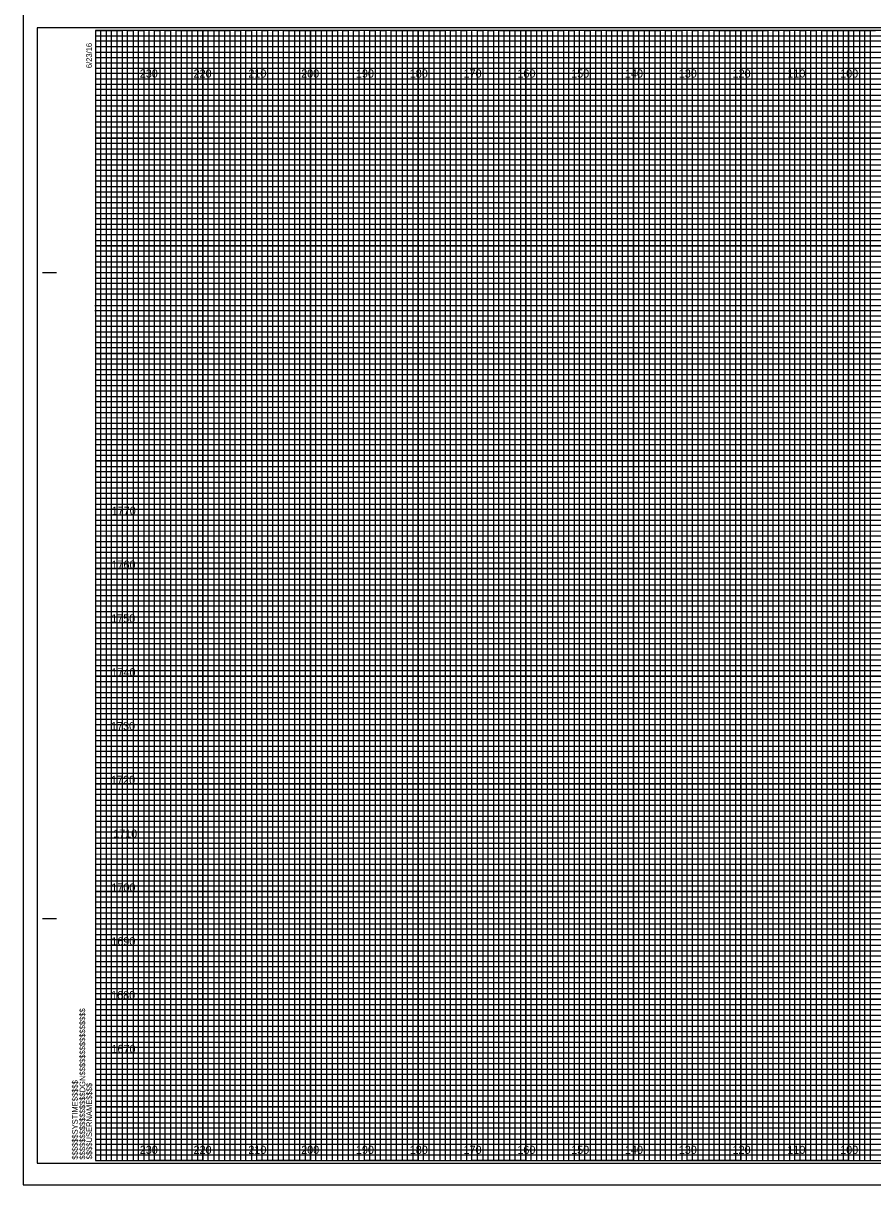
# Model space of a CAD drawing. Extents: x -13 to 1780, y -15 to 3284.
# Drawn here: x 726.7 to 884.6, y 431.6 to 647.5 of the extents above; entities that cross this region are included whole.
import ezdxf

# ---------------------------------------------------------------- set-up
doc = ezdxf.new("R2010")
doc.units = 0
for name, color, linetype in [('Prop Retaining Wall', 7, 'Continuous'), ('Prop SS Cut Line', 7, 'Continuous'), ('Prop SS Fill Line', 7, 'Continuous'), ('Prop SS Transition Line', 7, 'Continuous'), ('Prop XS Earthwork Shape', 7, 'Continuous'), ('Prop XS Noise Wall', 7, 'Continuous'), ('Prop XS Station Labels', 7, 'Continuous'), ('Raster_Level_0', 7, 'Continuous'), ('Scratch_Level_3', 7, 'Continuous'), ('Scratch_Level_7', 7, 'Continuous'), ('Typical Bridge Rail CELL', 7, 'Continuous')]:
    doc.layers.add(name, color=color, linetype=linetype)

msp = doc.modelspace()

# ---------------------------------------------------------------- linework, layer by layer
at = {"layer": 'Prop Retaining Wall'}
for p, q in [((730.26, 601.12), (732.76, 601.12)), ((730.36, 601.12), (732.86, 601.12)), ((730.26, 481.12), (732.76, 481.12)), ((730.36, 481.12), (732.86, 481.12)), ((740.06, 436.12), (740.06, 436.12)), ((740.06, 436.12), (740.06, 436.12)), ((740.06, 436.12), (740.06, 436.12)), ((740.06, 436.12), (740.06, 436.12)), ((740.06, 436.12), (740.06, 436.12)), ((740.06, 436.12), (740.06, 436.12)), ((740.06, 436.12), (740.06, 436.12))]:
    msp.add_line(p, q, dxfattribs=at)
msp.add_lwpolyline([(1060.06, 646.12), (740.06, 646.12), (740.06, 436.12), (1060.06, 436.12)], close=True, dxfattribs=at)
at = {"layer": 'Prop SS Cut Line'}
for points in [[(740.06, 646.12), (745.06, 646.12), (745.06, 436.12), (755.06, 436.12), (755.06, 646.12), (765.06, 646.12), (765.06, 436.12), (775.06, 436.12), (775.06, 646.12), (785.06, 646.12), (785.06, 436.12), (795.06, 436.12), (795.06, 646.12), (805.06, 646.12), (805.06, 436.12), (815.06, 436.12), (815.06, 646.12), (825.06, 646.12), (825.06, 436.12), (835.06, 436.12), (835.06, 646.12), (845.06, 646.12), (845.06, 436.12), (855.06, 436.12), (855.06, 646.12), (865.06, 646.12), (865.06, 436.12), (875.06, 436.12), (875.06, 646.12), (885.06, 646.12)], [(740.06, 641.12), (1015.06, 641.12)], [(740.06, 621.12), (1060.06, 621.12), (1060.06, 631.12), (740.06, 631.12)], [(740.06, 601.12), (1060.06, 601.12), (1060.06, 611.12), (740.06, 611.12)], [(740.06, 581.12), (1060.06, 581.12), (1060.06, 591.12), (740.06, 591.12)], [(740.06, 561.12), (1060.06, 561.12), (1060.06, 571.12), (740.06, 571.12)], [(740.06, 541.12), (1060.06, 541.12), (1060.06, 551.12), (740.06, 551.12)], [(740.06, 521.12), (1060.06, 521.12), (1060.06, 531.12), (740.06, 531.12)], [(740.06, 501.12), (1060.06, 501.12), (1060.06, 511.12), (740.06, 511.12)], [(740.06, 481.12), (1060.06, 481.12), (1060.06, 491.12), (740.06, 491.12)], [(740.06, 461.12), (1060.06, 461.12), (1060.06, 471.12), (740.06, 471.12)], [(740.06, 441.12), (1060.06, 441.12), (1060.06, 451.12), (740.06, 451.12)]]:
    msp.add_lwpolyline(points, dxfattribs=at)
at = {"layer": 'Prop SS Fill Line'}
for p, q in [((750.06, 646.12), (740.06, 646.12)), ((750.06, 436.12), (750.06, 646.12)), ((770.06, 646.12), (760.06, 646.12)), ((760.06, 646.12), (760.06, 436.12)), ((770.06, 436.12), (770.06, 646.12)), ((790.06, 646.12), (780.06, 646.12)), ((780.06, 646.12), (780.06, 436.12)), ((790.06, 436.12), (790.06, 646.12)), ((810.06, 646.12), (800.06, 646.12)), ((800.06, 646.12), (800.06, 436.12)), ((810.06, 436.12), (810.06, 646.12)), ((830.06, 646.12), (820.06, 646.12)), ((820.06, 646.12), (820.06, 436.12)), ((830.06, 436.12), (830.06, 646.12)), ((850.06, 646.12), (840.06, 646.12)), ((840.06, 646.12), (840.06, 436.12)), ((850.06, 436.12), (850.06, 646.12)), ((870.06, 646.12), (860.06, 646.12)), ((860.06, 646.12), (860.06, 436.12)), ((870.06, 436.12), (870.06, 646.12)), ((890.06, 646.12), (880.06, 646.12)), ((880.06, 646.12), (880.06, 436.12)), ((760.06, 436.12), (750.06, 436.12)), ((780.06, 436.12), (770.06, 436.12)), ((800.06, 436.12), (790.06, 436.12)), ((820.06, 436.12), (810.06, 436.12)), ((840.06, 436.12), (830.06, 436.12)), ((860.06, 436.12), (850.06, 436.12)), ((880.06, 436.12), (870.06, 436.12))]:
    msp.add_line(p, q, dxfattribs=at)
for points in [[(740.06, 636.12), (1060.06, 636.12), (1060.06, 626.12), (740.06, 626.12)], [(740.06, 616.12), (1060.06, 616.12), (1060.06, 606.12), (740.06, 606.12)], [(740.06, 596.12), (1060.06, 596.12), (1060.06, 586.12), (740.06, 586.12)], [(740.06, 576.12), (1060.06, 576.12), (1060.06, 566.12), (740.06, 566.12)], [(740.06, 556.12), (1060.06, 556.12), (1060.06, 546.12), (740.06, 546.12)], [(740.06, 536.12), (1060.06, 536.12), (1060.06, 526.12), (740.06, 526.12)], [(740.06, 516.12), (1060.06, 516.12), (1060.06, 506.12), (740.06, 506.12)], [(740.06, 496.12), (1060.06, 496.12), (1060.06, 486.12), (740.06, 486.12)], [(740.06, 476.12), (1060.06, 476.12), (1060.06, 466.12), (740.06, 466.12)], [(740.06, 456.12), (1060.06, 456.12), (1060.06, 446.12), (740.06, 446.12)]]:
    msp.add_lwpolyline(points, dxfattribs=at)
at = {"layer": 'Prop SS Transition Line'}
for p, q in [((740.06, 645.12), (1000.06, 645.12)), ((1000.06, 644.1), (740.06, 644.1)), ((740.06, 644.1), (740.06, 643.12)), ((740.06, 643.12), (1000.06, 643.12)), ((1000.06, 642.01), (740.06, 642.01)), ((740.06, 642.01), (740.06, 640.12)), ((740.06, 640.12), (1060.06, 640.12))]:
    msp.add_line(p, q, dxfattribs=at)
for points in [[(740.06, 639.12), (1010.06, 639.12), (1060.06, 639.12), (1060.06, 638.12), (740.06, 638.12)], [(740.06, 637.12), (1060.06, 637.12), (1060.06, 635.12), (740.06, 635.12)], [(740.06, 634.12), (1060.06, 634.12), (1060.06, 633.12), (740.06, 633.1)], [(740.06, 632.12), (1060.06, 632.12), (1060.06, 630.12), (740.06, 630.12)], [(740.06, 629.12), (1060.06, 629.12), (1060.06, 628.12), (740.06, 628.12)], [(740.06, 627.12), (1060.06, 627.12), (1060.06, 625.12), (740.06, 625.12)], [(740.06, 624.12), (1060.06, 624.12), (1060.06, 623.12), (740.06, 623.12)], [(740.06, 622.12), (1060.06, 622.12), (1060.06, 620.12), (740.06, 620.12)], [(740.06, 619.12), (1060.06, 619.12), (1060.06, 618.12), (740.06, 618.12)], [(740.06, 617.12), (1060.06, 617.12), (1060.06, 615.12), (740.06, 615.12)], [(740.06, 614.12), (1060.06, 614.12), (1060.06, 613.12), (740.06, 613.12)], [(740.06, 612.12), (1060.06, 612.12), (1060.06, 610.07), (1060.06, 609.12), (1060.06, 608.12), (740.06, 608.12)], [(740.06, 610.12), (1060.06, 610.12), (1060.06, 609.12), (740.06, 609.12)], [(740.06, 607.12), (1060.06, 607.12), (1060.06, 605.12), (740.06, 605.15)], [(740.06, 605.15), (1060.06, 605.12), (1060.06, 604.12), (740.06, 604.12)], [(740.06, 603.12), (1060.06, 603.12), (1060.06, 602.12), (740.06, 602.12)], [(740.06, 600.12), (1060.06, 600.12), (1060.06, 599.12), (740.06, 599.12)], [(740.06, 598.12), (1060.06, 598.12), (1060.06, 597.12), (740.06, 597.12)], [(739.99, 595.01), (1060.06, 595.01), (1060.06, 594), (739.99, 594)], [(740.06, 593.12), (1060.06, 593.12), (1060.06, 592.12), (740.06, 592.12)], [(740.06, 590.12), (1060.06, 590.12), (1060.06, 589.12), (740.06, 589.12)], [(740.06, 588.12), (1060.06, 588.12), (1060.06, 587.12), (740.06, 587.12)], [(740.06, 585.12), (1060.06, 585.12), (1060.06, 584.12), (740.06, 584.12)], [(740.06, 583.12), (1060.06, 583.12), (1060.06, 582.12), (740.06, 582.12)], [(740.06, 580.12), (1060.06, 580.12), (1060.06, 579.12), (740.06, 579.12)], [(740.06, 578.12), (1060.06, 578.12), (1060.06, 577.12), (740.06, 577.12)], [(740.06, 575.12), (1060.06, 575.12), (1060.05, 574.1), (740.06, 574.12)], [(740.06, 573.12), (1060.06, 573.12), (1060.06, 572.12), (740.06, 572.12)], [(740.06, 570.12), (1060.06, 570.12), (1060.06, 569.12), (740.06, 569.12)], [(740.06, 568.12), (1060.06, 568.12), (1060.06, 567.12), (740.06, 567.12)], [(740.06, 565.12), (1060.06, 565.12), (1060.06, 564.12), (740.06, 564.12)], [(740.06, 563.12), (1060.06, 563.12), (1060.06, 562.12), (740.06, 562.12)], [(740.06, 560.12), (1060.06, 560.12), (1060.06, 559.12), (740.06, 559.12)], [(740.06, 558.12), (1060.06, 558.12), (1060.06, 557.12), (740.06, 557.12)], [(740.06, 555.12), (1060.06, 555.12), (1060.06, 554.12), (740.06, 554.12)], [(740.06, 553.11), (1060.13, 553.03), (1060.06, 552.12), (740.06, 552.12)], [(740.06, 550.12), (1060.06, 550.12), (1060.06, 549.12), (740.06, 549.12)], [(740.06, 548.12), (1060.06, 548.12), (1060.06, 547.12), (740.06, 547.12)], [(740.06, 545.12), (1060.06, 545.12), (1060.06, 544.12), (740.06, 544.12)], [(740.06, 543.12), (1060.06, 543.12), (1060.06, 542.12), (740.06, 542.12)], [(740.06, 540.12), (1060.06, 540.12), (1060.06, 539.12), (740.06, 539.12)], [(740.06, 538.12), (1060.06, 538.12), (1060.06, 537.12), (740.06, 537.12)], [(740.06, 535.12), (1060.06, 535.12), (1060.06, 534.12), (740.06, 534.12)], [(740.06, 533.12), (1060.06, 533.12), (1060.06, 532.12), (740.06, 532.12)], [(740.06, 530.12), (1060.06, 530.12), (1060.06, 529.12), (740.06, 529.12)], [(740.06, 528.12), (1060.06, 528.12), (1060.06, 527.12), (740.06, 527.12)], [(740.06, 525.12), (1060.06, 525.12), (1060.06, 524.12), (740.06, 524.12)], [(740.06, 523.12), (1060.06, 523.12), (1060.06, 522.12), (740.06, 522.12)], [(740.06, 520.12), (1060.06, 520.12), (1060.06, 519.12), (740.06, 519.12)], [(740.06, 518.12), (1060.06, 518.12), (1060.06, 517.12), (740.06, 517.12)], [(740.06, 515.12), (1060.06, 515.12), (1060.05, 514.1), (740.06, 514.12)], [(740.06, 513.12), (1060.06, 513.12), (1060.06, 512.12), (740.06, 512.12)], [(740.06, 510.12), (1060.06, 510.12), (1060.06, 509.12), (740.06, 509.12)], [(740.06, 508.12), (1060.06, 508.12), (1060.06, 507.12), (740.06, 507.12)], [(740.06, 505.12), (1060.06, 505.12), (1060.06, 504.12), (740.06, 504.12)], [(740.06, 503.12), (1060.06, 503.12), (1060.06, 502.12), (740.06, 502.12)], [(740.06, 500.12), (1060.06, 500.12), (1060.06, 499.12), (740.06, 499.12)], [(740.06, 498.12), (1060.06, 498.12), (1060.06, 497.12), (740.06, 497.12)], [(740.06, 495.12), (1060.06, 495.12), (1060.06, 494.12), (740.06, 494.12)], [(740.06, 493.11), (1060.13, 493.03), (1060.06, 492.12), (740.06, 492.12)], [(740.06, 490.12), (1060.06, 490.12), (1060.06, 489.12), (740.06, 489.12)], [(740.06, 488.12), (1060.06, 488.12), (1060.06, 487.12), (740.06, 487.12)], [(740.06, 485.12), (1060.06, 485.12), (1060.06, 484.12), (740.06, 484.12)], [(740.06, 483.12), (1060.06, 483.12), (1060.06, 482.12), (740.06, 482.12)], [(740.06, 480.12), (1060.06, 480.12), (1060.06, 479.12), (740.06, 479.12)], [(740.06, 478.12), (1060.06, 478.12), (1060.06, 477.12), (740.06, 477.12)], [(740.06, 475.12), (1060.06, 475.12), (1060.06, 474.12), (740.06, 474.12)], [(740.06, 473.12), (1060.06, 473.12), (1060.06, 472.12), (740.06, 472.12)], [(740.06, 470.12), (1060.06, 470.12), (1060.06, 469.12), (740.06, 469.12)], [(740.06, 468.12), (1060.06, 468.12), (1060.06, 467.12), (740.06, 467.12)], [(740.06, 465.12), (1060.06, 465.12), (1060.06, 464.12), (740.06, 464.12)], [(740.06, 463.12), (1060.06, 463.12), (1060.06, 462.12), (740.06, 462.12)], [(740.06, 460.12), (1060.06, 460.12), (1060.06, 459.12), (740.06, 459.12)], [(740.06, 458.12), (1060.06, 458.12), (1060.06, 457.12), (740.06, 457.12)], [(740.06, 455.12), (1060.06, 455.12), (1060.06, 454.12), (740.06, 454.12)], [(740.06, 453.12), (1060.06, 453.12), (1060.06, 452.12), (740.06, 452.12)], [(740.06, 450.12), (1060.06, 450.12), (1060.06, 449.12), (740.06, 449.12)], [(740.06, 448.12), (1060.06, 448.12), (1060.06, 447.12), (740.06, 447.12)], [(740.06, 445.12), (1060.06, 445.12), (1060.06, 444.12), (740.06, 444.12)], [(740.06, 443.12), (1060.06, 443.12), (1060.06, 442.12), (740.06, 442.12)], [(740.06, 440.12), (1060.06, 440.12), (1060.06, 439.12), (740.06, 439.12)], [(740.06, 438.12), (1060.06, 438.12), (1060.06, 437.12), (740.06, 437.12)]]:
    msp.add_lwpolyline(points, dxfattribs=at)
at = {"layer": 'Prop XS Earthwork Shape'}
msp.add_lwpolyline([(726.66, 431.62), (1063.36, 431.62), (1063.36, 650.62), (726.66, 650.62)], close=True, dxfattribs=at)
at = {"layer": 'Prop XS Noise Wall'}
for p, q in [((750.06, 436.12), (750.06, 646.12)), ((760.06, 436.12), (760.06, 646.12)), ((770.06, 436.12), (770.06, 646.12)), ((780.06, 436.12), (780.06, 646.12)), ((790.06, 436.12), (790.06, 646.12)), ((800.06, 436.12), (800.06, 646.12)), ((810.06, 436.12), (810.06, 646.12)), ((820.06, 436.12), (820.06, 646.12)), ((830.06, 436.12), (830.06, 646.12)), ((840.06, 436.12), (840.06, 646.12)), ((850.06, 436.12), (850.06, 646.12)), ((860.06, 436.12), (860.06, 646.12)), ((870.06, 436.12), (870.06, 646.12)), ((880.06, 436.12), (880.06, 646.12)), ((740.06, 636.12), (1060.06, 636.12)), ((740.06, 626.12), (1060.06, 626.12)), ((740.06, 616.12), (1060.06, 616.12)), ((740.06, 606.12), (1060.06, 606.12)), ((740.06, 596.12), (1060.06, 596.12)), ((740.06, 586.12), (1060.06, 586.12)), ((740.06, 576.12), (1060.06, 576.12)), ((740.06, 566.12), (1060.06, 566.12)), ((740.06, 556.12), (1060.06, 556.12)), ((740.06, 546.12), (1060.06, 546.12)), ((740.06, 536.12), (1060.06, 536.12)), ((740.06, 526.12), (1060.06, 526.12)), ((740.06, 516.12), (1060.06, 516.12)), ((740.06, 506.12), (1060.06, 506.12)), ((740.06, 496.12), (1060.06, 496.12)), ((740.06, 486.12), (1060.06, 486.12)), ((740.06, 476.12), (1060.06, 476.12)), ((740.06, 466.12), (1060.06, 466.12)), ((740.06, 456.12), (1060.06, 456.12)), ((740.06, 446.12), (1060.06, 446.12))]:
    msp.add_line(p, q, dxfattribs=at)
at = {"layer": 'Prop XS Station Labels'}
for p, q in [((726.66, 650.62), (726.66, 431.62)), ((726.66, 431.62), (1063.36, 431.62))]:
    msp.add_line(p, q, dxfattribs=at)
at = {"layer": 'Scratch_Level_7'}
msp.add_lwpolyline([(729.26, 435.62), (1062.46, 435.62), (1062.46, 646.62), (729.26, 646.62)], close=True, dxfattribs=at)
at = {"layer": 'Typical Bridge Rail CELL'}
for points in [[(740.06, 436.12), (741.06, 436.12), (741.06, 646.12), (742.06, 646.12), (742.06, 436.12)], [(742.06, 436.12), (743.06, 436.12), (743.06, 646.12), (744.06, 646.12), (744.06, 436.12)], [(745.06, 436.12), (746.06, 436.12), (746.06, 646.12), (747.06, 646.12), (747.06, 436.12)], [(747.06, 436.12), (748.06, 436.12), (748.06, 646.12), (749.06, 646.12), (749.06, 436.12)], [(750.06, 436.12), (751.06, 436.12), (751.06, 646.12), (752.06, 646.12), (752.06, 436.12)], [(752.06, 436.12), (753.06, 436.12), (753.06, 646.12), (754.06, 646.12), (754.06, 436.12)], [(755.06, 436.12), (756.06, 436.12), (756.06, 646.12), (757.06, 646.12), (757.06, 436.12)], [(757.06, 436.12), (758.06, 436.12), (758.06, 646.12), (759.06, 646.12), (759.06, 436.12)], [(760.06, 436.12), (761.06, 436.12), (761.06, 646.12), (762.06, 646.12), (762.06, 436.12)], [(762.06, 436.12), (763.06, 436.12), (763.06, 646.12), (764.06, 646.12), (764.06, 436.12)], [(765.06, 436.12), (766.06, 436.12), (766.06, 646.12), (767.06, 646.12), (767.06, 436.12)], [(767.06, 436.12), (768.06, 436.12), (768.06, 646.12), (769.06, 646.12), (769.06, 436.12)], [(770.06, 436.12), (771.06, 436.12), (771.06, 646.12), (772.06, 646.12), (772.06, 436.12)], [(772.06, 436.12), (773.06, 436.12), (773.06, 646.12), (774.06, 646.12), (774.06, 436.12)], [(775.06, 436.12), (776.06, 436.12), (776.06, 646.12), (777.06, 646.12), (777.06, 436.12)], [(777.06, 436.12), (778.06, 436.12), (778.06, 646.12), (779.06, 646.12), (779.06, 436.12)], [(780.06, 436.12), (781.06, 436.12), (781.06, 646.12), (782.06, 646.12), (782.06, 436.12)], [(782.06, 436.12), (783.06, 436.12), (783.06, 646.12), (784.06, 646.12), (784.06, 436.12)], [(785.06, 436.12), (786.06, 436.12), (786.06, 646.12), (787.06, 646.12), (787.06, 436.12)], [(787.06, 436.12), (788.06, 436.12), (788.06, 646.12), (789.06, 646.12), (789.06, 436.12)], [(790.06, 436.12), (791.06, 436.12), (791.06, 646.12), (792.06, 646.12), (792.06, 436.12)], [(792.06, 436.12), (793.06, 436.12), (793.06, 646.12), (794.06, 646.12), (794.06, 436.12)], [(795.06, 436.12), (796.06, 436.12), (796.06, 646.12), (797.06, 646.12), (797.06, 436.12)], [(797.06, 436.12), (798.06, 436.12), (798.06, 646.12), (799.06, 646.12), (799.06, 436.12)], [(800.06, 436.12), (801.06, 436.12), (801.06, 646.12), (802.06, 646.12), (802.06, 436.12)], [(802.06, 436.12), (803.06, 436.12), (803.06, 646.12), (804.06, 646.12), (804.06, 436.12)], [(805.06, 436.12), (806.06, 436.12), (806.06, 646.12), (807.06, 646.12), (807.06, 436.12)], [(807.06, 436.12), (808.06, 436.12), (808.06, 646.12), (809.06, 646.12), (809.06, 436.12)], [(810.06, 436.12), (811.06, 436.12), (811.06, 646.12), (812.06, 646.12), (812.06, 436.12)], [(812.06, 436.12), (813.06, 436.12), (813.06, 646.12), (814.06, 646.12), (814.06, 436.12)], [(815.06, 436.12), (816.06, 436.12), (816.06, 646.12), (817.06, 646.12), (817.06, 436.12)], [(817.06, 436.12), (818.06, 436.12), (818.06, 646.12), (819.06, 646.12), (819.06, 436.12)], [(820.06, 436.12), (821.06, 436.12), (821.06, 646.12), (822.06, 646.12), (822.06, 436.12)], [(822.06, 436.12), (823.06, 436.12), (823.06, 646.12), (824.06, 646.12), (824.06, 436.12)], [(825.06, 436.12), (826.06, 436.12), (826.06, 646.12), (827.06, 646.12), (827.06, 436.12)], [(827.06, 436.12), (828.06, 436.12), (828.06, 646.12), (829.06, 646.12), (829.06, 436.12)], [(830.06, 436.12), (831.06, 436.12), (831.06, 646.12), (832.06, 646.12), (832.06, 436.12)], [(832.06, 436.12), (833.06, 436.12), (833.06, 646.12), (834.06, 646.12), (834.06, 436.12)], [(835.06, 436.12), (836.06, 436.12), (836.06, 646.12), (837.06, 646.12), (837.06, 436.12)], [(837.06, 436.12), (838.06, 436.12), (838.06, 646.12), (839.06, 646.12), (839.06, 436.12)], [(840.06, 436.12), (841.06, 436.12), (841.06, 646.12), (842.06, 646.12), (842.06, 436.12)], [(842.06, 436.12), (843.06, 436.12), (843.06, 646.12), (844.06, 646.12), (844.06, 436.12)], [(845.06, 436.12), (846.06, 436.12), (846.06, 646.12), (847.06, 646.12), (847.06, 436.12)], [(847.06, 436.12), (848.06, 436.12), (848.06, 646.12), (849.06, 646.12), (849.06, 436.12)], [(850.06, 436.12), (851.06, 436.12), (851.06, 646.12), (852.06, 646.12), (852.06, 436.12)], [(852.06, 436.12), (853.06, 436.12), (853.06, 646.12), (854.06, 646.12), (854.06, 436.12)], [(855.06, 436.12), (856.06, 436.12), (856.06, 646.12), (857.06, 646.12), (857.06, 436.12)], [(857.06, 436.12), (858.06, 436.12), (858.06, 646.12), (859.06, 646.12), (859.06, 436.12)], [(860.06, 436.12), (861.06, 436.12), (861.06, 646.12), (862.06, 646.12), (862.06, 436.12)], [(862.06, 436.12), (863.06, 436.12), (863.06, 646.12), (864.06, 646.12), (864.06, 436.12)], [(865.06, 436.12), (866.06, 436.12), (866.06, 646.12), (867.06, 646.12), (867.06, 436.12)], [(867.06, 436.12), (868.06, 436.12), (868.06, 646.12), (869.06, 646.12), (869.06, 436.12)], [(870.06, 436.12), (871.06, 436.12), (871.06, 646.12), (872.06, 646.12), (872.06, 436.12)], [(872.06, 436.12), (873.06, 436.12), (873.06, 646.12), (874.06, 646.12), (874.06, 436.12)], [(875.06, 436.12), (876.06, 436.12), (876.06, 646.12), (877.06, 646.12), (877.06, 436.12)], [(877.06, 436.12), (878.06, 436.12), (878.06, 646.12), (879.06, 646.12), (879.06, 436.12)], [(880.06, 436.12), (881.06, 436.12), (881.06, 646.12), (882.06, 646.12), (882.06, 436.12)], [(882.06, 436.12), (883.06, 436.12), (883.06, 646.12), (884.06, 646.12), (884.06, 436.12)]]:
    msp.add_lwpolyline(points, dxfattribs=at)

# ---------------------------------------------------------------- texts
at = {"layer": 'Prop Retaining Wall'}
for s, p in [('6/23/16', (739.41, 639.12)), ('$$$$$$$$$$$$$$$$DGN$$$$$$$$$$$$$$$$', (738.18, 436.3)), ('$$$$$$SYSTIME$$$$$', (736.8, 436.3)), ('$$$$USERNAME$$$$', (739.44, 436.35))]:
    msp.add_text(s, height=1.05, rotation=90, dxfattribs=at).set_placement(p)
at = {"layer": 'Raster_Level_0'}
for s, p in [('230', (748.32, 637.37)), ('220', (758.32, 637.37)), ('210', (768.5, 637.37)), ('200', (778.32, 637.37)), ('190', (788.5, 637.37)), ('180', (798.5, 637.37)), ('170', (808.5, 637.37)), ('160', (818.5, 637.37)), ('150', (828.5, 637.37)), ('140', (838.5, 637.37)), ('130', (848.5, 637.37)), ('120', (858.5, 637.37)), ('110', (868.68, 637.37)), ('100', (878.5, 637.37)), ('230', (748.32, 437.37)), ('220', (758.32, 437.37)), ('210', (768.5, 437.37)), ('200', (778.32, 437.37)), ('190', (788.5, 437.37)), ('180', (798.5, 437.37)), ('170', (808.5, 437.37)), ('160', (818.5, 437.37)), ('150', (828.5, 437.37)), ('140', (838.5, 437.37)), ('130', (848.5, 437.37)), ('120', (858.5, 437.37)), ('110', (868.68, 437.37)), ('100', (878.5, 437.37))]:
    msp.add_text(s, height=1.5, dxfattribs=at).set_placement(p)
at = {"layer": 'Scratch_Level_3'}
for s, p in [('1770', (743.1, 556.12)), ('1760', (743.06, 546.12)), ('1750', (743.01, 536.12)), ('1740', (743.06, 526.12)), ('1730', (742.98, 516.12)), ('1720', (742.99, 506.12)), ('1710', (743.37, 496.12)), ('1700', (743.04, 486.12)), ('1690', (743.03, 476.12)), ('1680', (743, 466.12)), ('1670', (743.06, 456.12))]:
    msp.add_text(s, height=1.5, dxfattribs=at).set_placement(p)

doc.saveas('drawing.dxf')
